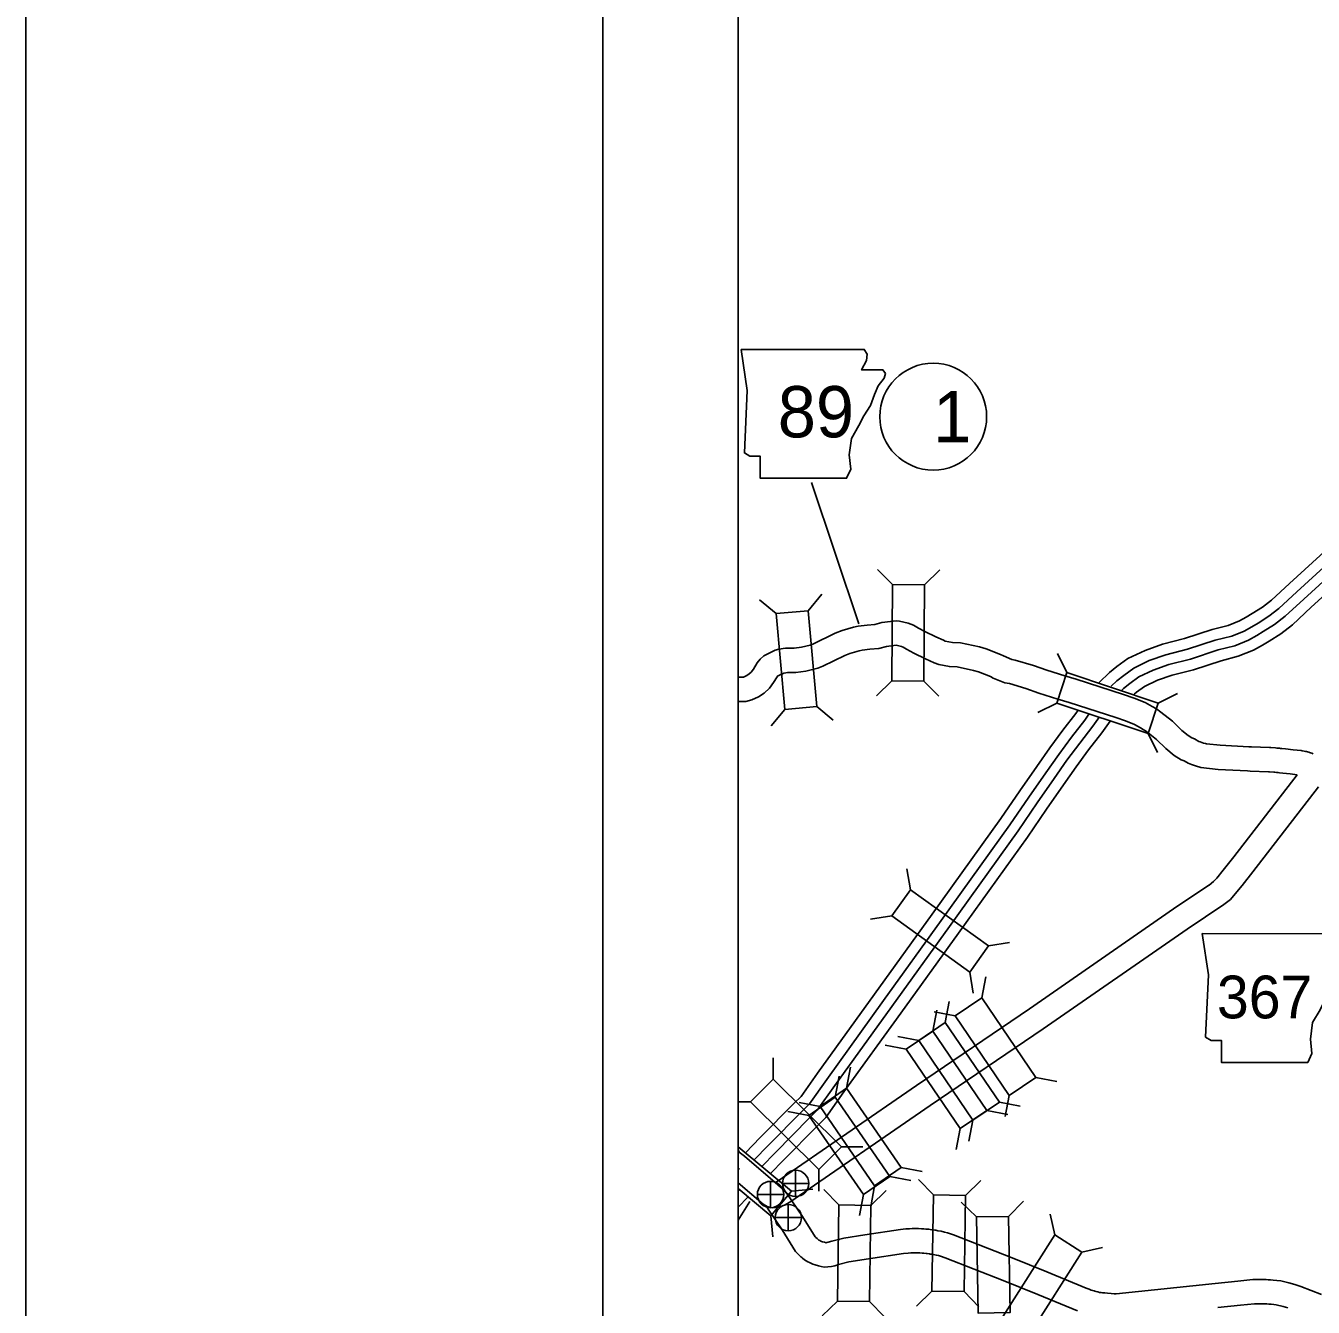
# Model space of a CAD drawing. Extents: x 1367863 to 1368197, y 380048 to 380261.
# Drawn here: x 1367863.39 to 1367891.07, y 380206.32 to 380233.88 of the extents above; entities that cross this region are included whole.
import ezdxf

# ---------------------------------------------------------------- set-up
doc = ezdxf.new("R2010")
doc.units = 0
for name, color, linetype in [('Level 10', 7, 'Continuous'), ('Level 15', 7, 'Continuous'), ('Level 20', 7, 'Continuous'), ('Level 21', 7, 'Continuous'), ('Level 26', 7, 'Continuous'), ('Level 27', 7, 'Continuous'), ('Level 58', 7, 'Continuous'), ('R_Border', 7, 'Continuous'), ('R_No Plot', 7, 'Continuous')]:
    doc.layers.add(name, color=color, linetype=linetype)

msp = doc.modelspace()

# ---------------------------------------------------------------- linework, layer by layer
at = {"layer": 'Level 10'}
for points in [[(1367878.711, 380219.865), (1367878.808, 380219.866), (1367878.824, 380219.87), (1367878.896, 380219.905), (1367878.945, 380219.936), (1367878.989, 380219.977), (1367879.035, 380220.042), (1367879.119, 380220.176), (1367879.181, 380220.254), (1367879.264, 380220.326), (1367879.348, 380220.373), (1367879.507, 380220.446), (1367879.586, 380220.469), (1367879.729, 380220.489), (1367879.913, 380220.493), (1367880.069, 380220.512), (1367880.26, 380220.557), (1367880.312, 380220.578), (1367880.792, 380220.814), (1367880.945, 380220.871), (1367881.189, 380220.941), (1367881.287, 380220.961), (1367881.48, 380220.988), (1367881.645, 380221.003), (1367881.8, 380221.042), (1367882.105, 380221.079), (1367882.175, 380221.073), (1367882.365, 380221.027), (1367882.481, 380220.989), (1367882.588, 380220.923), (1367882.725, 380220.848), (1367882.959, 380220.733), (1367883.123, 380220.66), (1367883.162, 380220.645), (1367883.317, 380220.616), (1367883.49, 380220.606), (1367883.896, 380220.519), (1367884.042, 380220.476), (1367884.35, 380220.357), (1367884.412, 380220.324), (1367884.593, 380220.251), (1367884.667, 380220.236), (1367885.057, 380220.121), (1367885.346, 380220.015), (1367885.729, 380219.893), (1367885.974, 380219.823), (1367886.995, 380219.495), (1367887.221, 380219.417), (1367887.459, 380219.32), (1367887.612, 380219.236)], [(1367878.711, 380219.343), (1367878.875, 380219.344), (1367879.006, 380219.378), (1367879.149, 380219.447), (1367879.267, 380219.522), (1367879.383, 380219.631), (1367879.469, 380219.75), (1367879.547, 380219.875), (1367879.561, 380219.893), (1367879.565, 380219.896), (1367879.584, 380219.906), (1367879.691, 380219.956), (1367879.697, 380219.957), (1367879.77, 380219.968), (1367879.951, 380219.971), (1367880.161, 380219.998), (1367880.419, 380220.058), (1367880.526, 380220.102), (1367880.999, 380220.333), (1367881.109, 380220.374), (1367881.313, 380220.433), (1367881.376, 380220.446), (1367881.54, 380220.469), (1367881.733, 380220.486), (1367881.897, 380220.528), (1367882.104, 380220.553), (1367882.222, 380220.524), (1367882.259, 380220.512), (1367882.325, 380220.471), (1367882.485, 380220.384), (1367882.737, 380220.26), (1367882.925, 380220.176), (1367883.023, 380220.14), (1367883.252, 380220.097), (1367883.419, 380220.087), (1367883.767, 380220.012), (1367883.873, 380219.981), (1367884.135, 380219.88), (1367884.194, 380219.849), (1367884.442, 380219.749), (1367884.54, 380219.729), (1367884.893, 380219.625), (1367885.176, 380219.521), (1367885.578, 380219.392), (1367885.823, 380219.323), (1367886.83, 380218.999), (1367887.038, 380218.928), (1367887.233, 380218.849), (1367887.358, 380218.779)], [(1367887.612, 380219.236), (1367887.699, 380219.184), (1367887.797, 380219.117), (1367888.044, 380218.919), (1367888.25, 380218.724), (1367888.385, 380218.61), (1367888.463, 380218.565), (1367888.519, 380218.543), (1367888.616, 380218.488), (1367888.641, 380218.477), (1367888.714, 380218.452), (1367888.755, 380218.445), (1367888.776, 380218.437), (1367889.07, 380218.406), (1367889.685, 380218.373), (1367889.744, 380218.37), (1367890.135, 380218.353), (1367890.161, 380218.352), (1367890.258, 380218.346), (1367890.286, 380218.344), (1367890.323, 380218.341), (1367890.346, 380218.339), (1367890.367, 380218.337), (1367890.397, 380218.334), (1367890.473, 380218.326), (1367890.638, 380218.307), (1367890.81, 380218.288), (1367890.833, 380218.285), (1367890.875, 380218.278), (1367890.905, 380218.272), (1367890.927, 380218.267), (1367890.952, 380218.26), (1367890.975, 380218.253), (1367890.993, 380218.247), (1367891.013, 380218.241), (1367891.039, 380218.231), (1367891.072, 380218.218)], [(1367887.358, 380218.779), (1367887.418, 380218.744), (1367887.486, 380218.697), (1367887.701, 380218.525), (1367887.901, 380218.334), (1367888.083, 380218.181), (1367888.235, 380218.093), (1367888.294, 380218.07), (1367888.383, 380218.02), (1367888.453, 380217.99), (1367888.582, 380217.945), (1367888.616, 380217.939), (1367888.656, 380217.924), (1367889.029, 380217.885), (1367889.657, 380217.852), (1367889.719, 380217.849), (1367890.111, 380217.832), (1367890.132, 380217.831), (1367890.222, 380217.825), (1367890.246, 380217.823), (1367890.28, 380217.82), (1367890.3, 380217.819), (1367890.318, 380217.817), (1367890.345, 380217.814), (1367890.416, 380217.807), (1367890.579, 380217.788), (1367890.727, 380217.771)], [(1367878.731, 380209.657), (1367878.842, 380209.568), (1367879.505, 380209.003), (1367879.544, 380209.024), (1367882.545, 380211.089), (1367884.972, 380212.738), (1367888.068, 380214.884), (1367888.829, 380215.392), (1367888.835, 380215.395), (1367888.931, 380215.471), (1367889.001, 380215.548), (1367889.136, 380215.715), (1367889.363, 380216.003), (1367890.727, 380217.771)], [(1367878.711, 380208.994), (1367879.246, 380208.537), (1367879.335, 380208.483), (1367879.446, 380208.46), (1367879.517, 380208.465), (1367879.586, 380208.474), (1367879.703, 380208.516), (1367879.817, 380208.577), (1367882.84, 380210.657), (1367885.268, 380212.307), (1367888.361, 380214.452), (1367889.151, 380214.979), (1367889.29, 380215.089), (1367889.397, 380215.208), (1367889.544, 380215.389), (1367889.775, 380215.682), (1367891.186, 380217.512)], [(1367878.711, 380209.714), (1367878.731, 380209.657)], [(1367879.505, 380209.003), (1367879.616, 380208.905), (1367879.653, 380208.876), (1367879.743, 380208.784), (1367879.864, 380208.605)], [(1367879.26, 380208.52), (1367879.295, 380208.492), (1367879.306, 380208.484), (1367879.337, 380208.452), (1367879.656, 380207.983), (1367879.945, 380207.521), (1367879.983, 380207.478), (1367880.02, 380207.437), (1367880.042, 380207.421), (1367880.059, 380207.405), (1367880.075, 380207.391), (1367880.093, 380207.375), (1367880.138, 380207.341), (1367880.173, 380207.32), (1367880.207, 380207.299), (1367880.239, 380207.281), (1367880.271, 380207.264), (1367880.317, 380207.246), (1367880.367, 380207.228), (1367880.435, 380207.211), (1367880.496, 380207.195), (1367880.561, 380207.184), (1367880.635, 380207.185), (1367880.718, 380207.197), (1367880.784, 380207.213), (1367880.866, 380207.239), (1367881.086, 380207.295), (1367881.512, 380207.359), (1367882.266, 380207.472), (1367882.362, 380207.482), (1367882.421, 380207.486), (1367882.48, 380207.489), (1367882.492, 380207.49), (1367882.528, 380207.49), (1367882.561, 380207.489), (1367882.617, 380207.486), (1367882.667, 380207.482), (1367882.702, 380207.48), (1367882.749, 380207.475), (1367882.773, 380207.472), (1367882.813, 380207.468), (1367882.824, 380207.467), (1367882.839, 380207.463), (1367882.871, 380207.458), (1367882.908, 380207.452), (1367882.966, 380207.441), (1367883.016, 380207.43), (1367883.057, 380207.418), (1367883.161, 380207.384), (1367884.408, 380206.896), (1367885.15, 380206.595), (1367886.004, 380206.243)], [(1367879.864, 380208.605), (1367880.093, 380208.268), (1367880.364, 380207.835), (1367880.371, 380207.828), (1367880.373, 380207.825), (1367880.379, 380207.821), (1367880.406, 380207.795), (1367880.419, 380207.785), (1367880.426, 380207.779), (1367880.432, 380207.774), (1367880.446, 380207.765), (1367880.468, 380207.752), (1367880.488, 380207.741), (1367880.493, 380207.738), (1367880.504, 380207.734), (1367880.521, 380207.728), (1367880.562, 380207.717), (1367880.601, 380207.707), (1367880.617, 380207.71), (1367880.642, 380207.716), (1367880.723, 380207.742), (1367880.982, 380207.808), (1367881.435, 380207.876), (1367882.201, 380207.99), (1367882.316, 380208.002), (1367882.389, 380208.008), (1367882.451, 380208.011), (1367882.473, 380208.012), (1367882.538, 380208.012), (1367882.586, 380208.01), (1367882.649, 380208.007), (1367882.702, 380208.003), (1367882.743, 380208.001), (1367882.808, 380207.995), (1367882.837, 380207.991), (1367882.869, 380207.987), (1367882.904, 380207.984), (1367882.935, 380207.977), (1367882.956, 380207.974), (1367883.001, 380207.966), (1367883.071, 380207.953), (1367883.147, 380207.936), (1367883.212, 380207.917), (1367883.336, 380207.877), (1367884.601, 380207.381), (1367885.348, 380207.078), (1367886.193, 380206.731), (1367886.255, 380206.708), (1367886.301, 380206.69), (1367886.328, 380206.681), (1367886.36, 380206.669), (1367886.378, 380206.664), (1367886.403, 380206.657), (1367886.438, 380206.649), (1367886.476, 380206.639), (1367886.495, 380206.635), (1367886.51, 380206.634), (1367886.544, 380206.631), (1367886.595, 380206.626), (1367886.648, 380206.621), (1367886.726, 380206.614), (1367886.795, 380206.608), (1367886.832, 380206.608), (1367888.966, 380206.831), (1367889.451, 380206.882), (1367889.771, 380206.916), (1367889.837, 380206.918), (1367889.868, 380206.918), (1367889.91, 380206.918), (1367889.954, 380206.918), (1367890.005, 380206.918), (1367890.063, 380206.914), (1367890.102, 380206.912), (1367890.156, 380206.908), (1367890.208, 380206.905), (1367890.287, 380206.896), (1367890.372, 380206.885), (1367890.546, 380206.842), (1367890.679, 380206.81), (1367890.802, 380206.763), (1367891.251, 380206.597)], [(1367889.021, 380206.312), (1367889.505, 380206.363), (1367889.808, 380206.395), (1367889.847, 380206.396), (1367889.866, 380206.396), (1367889.91, 380206.396), (1367889.954, 380206.396), (1367889.984, 380206.396), (1367890.036, 380206.392), (1367890.071, 380206.391), (1367890.119, 380206.387), (1367890.165, 380206.384), (1367890.224, 380206.378), (1367890.275, 380206.371), (1367890.423, 380206.335), (1367890.523, 380206.31)]]:
    msp.add_lwpolyline(points, dxfattribs=at)
at = {"layer": 'Level 15'}
for points in [[(1367886.472, 380219.756), (1367886.689, 380219.965), (1367886.852, 380220.097), (1367887.089, 380220.27), (1367887.456, 380220.444), (1367887.832, 380220.579), (1367888.303, 380220.698), (1367888.897, 380220.891), (1367889.245, 380220.981), (1367889.485, 380221.076), (1367889.628, 380221.157), (1367889.759, 380221.236), (1367889.978, 380221.373), (1367890.175, 380221.525), (1367890.559, 380221.882), (1367891.967, 380223.166), (1367892.459, 380223.625), (1367893.445, 380224.541)], [(1367886.73, 380219.672), (1367886.848, 380219.786), (1367886.998, 380219.907), (1367887.212, 380220.063), (1367887.548, 380220.223), (1367887.902, 380220.35), (1367888.37, 380220.468), (1367888.964, 380220.661), (1367889.319, 380220.752), (1367889.589, 380220.859), (1367889.749, 380220.95), (1367889.885, 380221.032), (1367890.115, 380221.177), (1367890.33, 380221.342), (1367890.721, 380221.706), (1367892.129, 380222.99), (1367892.622, 380223.449), (1367893.616, 380224.373)], [(1367886.958, 380219.59), (1367886.992, 380219.623), (1367887.13, 380219.734), (1367887.324, 380219.875), (1367887.632, 380220.021), (1367887.966, 380220.142), (1367888.43, 380220.258), (1367889.025, 380220.452), (1367889.386, 380220.545), (1367889.683, 380220.662), (1367889.859, 380220.763), (1367889.999, 380220.847), (1367890.24, 380220.998), (1367890.471, 380221.176), (1367890.868, 380221.546), (1367892.277, 380222.83), (1367892.771, 380223.29), (1367893.784, 380224.233)], [(1367887.225, 380219.503), (1367887.276, 380219.544), (1367887.447, 380219.669), (1367887.724, 380219.8), (1367888.036, 380219.912), (1367888.496, 380220.028), (1367889.092, 380220.222), (1367889.461, 380220.317), (1367889.787, 380220.446), (1367889.98, 380220.556), (1367890.124, 380220.643), (1367890.377, 380220.801), (1367890.626, 380220.993), (1367891.031, 380221.37), (1367892.439, 380222.654), (1367892.934, 380223.115), (1367893.948, 380224.058)], [(1367878.866, 380209.64), (1367879.181, 380209.969), (1367879.915, 380210.708), (1367880.06, 380210.852), (1367880.417, 380211.354), (1367881.641, 380213.052), (1367882.88, 380214.773), (1367884.355, 380216.827), (1367884.763, 380217.427), (1367885.13, 380217.95), (1367885.407, 380218.346), (1367885.686, 380218.725), (1367885.968, 380219.089), (1367886.015, 380219.156)], [(1367879.051, 380209.486), (1367879.353, 380209.801), (1367880.084, 380210.539), (1367880.243, 380210.696), (1367880.612, 380211.215), (1367881.835, 380212.912), (1367883.074, 380214.633), (1367884.552, 380216.69), (1367884.96, 380217.291), (1367885.326, 380217.813), (1367885.601, 380218.207), (1367885.877, 380218.58), (1367886.16, 380218.946), (1367886.251, 380219.075)], [(1367879.218, 380209.347), (1367879.509, 380209.649), (1367880.238, 380210.385), (1367880.41, 380210.555), (1367880.789, 380211.088), (1367882.011, 380212.784), (1367883.251, 380214.506), (1367884.73, 380216.565), (1367885.14, 380217.167), (1367885.505, 380217.688), (1367885.778, 380218.08), (1367886.051, 380218.449), (1367886.335, 380218.817), (1367886.476, 380219.014)], [(1367879.403, 380209.193), (1367879.68, 380209.482), (1367880.407, 380210.216), (1367880.593, 380210.399), (1367880.984, 380210.948), (1367882.206, 380212.645), (1367883.445, 380214.366), (1367884.926, 380216.428), (1367885.337, 380217.031), (1367885.701, 380217.551), (1367885.972, 380217.94), (1367886.242, 380218.305), (1367886.527, 380218.674), (1367886.706, 380218.924)], [(1367878.711, 380208.819), (1367878.743, 380208.852)], [(1367878.711, 380208.474), (1367878.918, 380208.689)]]:
    msp.add_lwpolyline(points, dxfattribs=at)
at = {"layer": 'Level 20'}
for p, q in [((1367882.024, 380221.859), (1367881.701, 380222.186)), ((1367882.713, 380221.853), (1367883.041, 380222.176)), ((1367879.524, 380221.234), (1367879.171, 380221.529)), ((1367880.211, 380221.297), (1367880.505, 380221.65)), ((1367885.778, 380219.966), (1367885.572, 380220.377)), ((1367882.009, 380219.79), (1367881.681, 380219.467)), ((1367882.698, 380219.785), (1367883.021, 380219.458)), ((1367885.56, 380219.312), (1367885.148, 380219.106)), ((1367887.74, 380219.311), (1367888.151, 380219.516)), ((1367879.711, 380219.174), (1367879.416, 380218.821)), ((1367880.397, 380219.236), (1367880.75, 380218.942)), ((1367887.522, 380218.657), (1367887.727, 380218.246)), ((1367882.411, 380215.297), (1367882.338, 380215.75)), ((1367882.009, 380214.737), (1367881.555, 380214.663)), ((1367884.09, 380214.088), (1367884.544, 380214.162)), ((1367883.687, 380213.528), (1367883.761, 380213.075)), ((1367883.945, 380212.974), (1367884.031, 380213.426)), ((1367882.892, 380212.259), (1367882.978, 380212.711)), ((1367883.375, 380212.587), (1367882.923, 380212.673)), ((1367883.161, 380212.442), (1367883.247, 380212.893)), ((1367882.591, 380212.054), (1367882.139, 380212.14)), ((1367882.322, 380211.872), (1367881.87, 380211.958)), ((1367879.46, 380211.224), (1367879.458, 380211.684)), ((1367880.796, 380210.836), (1367880.879, 380211.288)), ((1367881.037, 380211.028), (1367881.121, 380211.48)), ((1367885.108, 380211.263), (1367885.559, 380211.177)), ((1367878.974, 380210.734), (1367878.711, 380210.733)), ((1367880.469, 380210.637), (1367880.017, 380210.72)), ((1367884.324, 380210.731), (1367884.775, 380210.644)), ((1367884.537, 380210.876), (1367884.451, 380210.424)), ((1367880.228, 380210.445), (1367879.776, 380210.529)), ((1367884.055, 380210.548), (1367884.506, 380210.462)), ((1367883.484, 380210.16), (1367883.398, 380209.709)), ((1367883.753, 380210.343), (1367883.667, 380209.892)), ((1367880.929, 380209.768), (1367881.389, 380209.77)), ((1367882.21, 380209.323), (1367882.662, 380209.24)), ((1367880.444, 380209.278), (1367880.446, 380208.818)), ((1367881.968, 380209.132), (1367882.42, 380209.048)), ((1367882.906, 380208.734), (1367882.586, 380209.063)), ((1367879.854, 380208.817), (1367880.312, 380208.859)), ((1367880.874, 380208.521), (1367880.554, 380208.851)), ((1367881.642, 380208.933), (1367881.558, 380208.481)), ((1367881.564, 380208.51), (1367881.894, 380208.83)), ((1367883.595, 380208.723), (1367883.925, 380209.043)), ((1367881.4, 380208.741), (1367881.317, 380208.289)), ((1367883.834, 380208.262), (1367883.504, 380208.582)), ((1367884.523, 380208.272), (1367884.843, 380208.602)), ((1367879.413, 380208.287), (1367879.454, 380207.83)), ((1367885.514, 380207.873), (1367885.413, 380208.322)), ((1367886.096, 380207.504), (1367886.545, 380207.604)), ((1367882.875, 380206.665), (1367882.545, 380206.345)), ((1367883.565, 380206.655), (1367883.885, 380206.325)), ((1367880.842, 380206.452), (1367880.512, 380206.132)), ((1367881.532, 380206.442), (1367881.852, 380206.112))]:
    msp.add_line(p, q, dxfattribs=at)
for points in [[(1367882.024, 380221.859), (1367882.009, 380219.79), (1367882.698, 380219.785), (1367882.713, 380221.853)], [(1367879.524, 380221.234), (1367879.711, 380219.174), (1367880.397, 380219.236), (1367880.211, 380221.297)], [(1367887.74, 380219.311), (1367885.778, 380219.966), (1367885.56, 380219.312), (1367887.522, 380218.657)], [(1367882.009, 380214.737), (1367883.687, 380213.528), (1367884.09, 380214.088), (1367882.411, 380215.297)], [(1367883.375, 380212.587), (1367884.537, 380210.876), (1367885.108, 380211.263), (1367883.945, 380212.974)], [(1367882.591, 380212.054), (1367883.753, 380210.343), (1367884.324, 380210.731), (1367883.161, 380212.442)], [(1367884.055, 380210.548), (1367882.892, 380212.259), (1367882.322, 380211.872), (1367883.484, 380210.16)], [(1367880.929, 380209.768), (1367879.46, 380211.224), (1367878.974, 380210.734), (1367880.444, 380209.278)], [(1367882.21, 380209.323), (1367881.037, 380211.028), (1367880.469, 380210.637), (1367881.642, 380208.933)], [(1367880.228, 380210.445), (1367881.4, 380208.741), (1367881.968, 380209.132), (1367880.796, 380210.836)], [(1367881.532, 380206.442), (1367881.564, 380208.51), (1367880.874, 380208.521), (1367880.842, 380206.452)], [(1367882.906, 380208.734), (1367882.875, 380206.665), (1367883.565, 380206.655), (1367883.595, 380208.723)], [(1367883.834, 380208.262), (1367883.865, 380206.193), (1367884.555, 380206.204), (1367884.523, 380208.272)], [(1367885.514, 380207.873), (1367884.406, 380206.126), (1367884.988, 380205.757), (1367886.096, 380207.504)]]:
    msp.add_lwpolyline(points, close=True, dxfattribs=at)
msp.add_lwpolyline([(1367878.711, 380208.872), (1367879.413, 380208.287), (1367879.854, 380208.817), (1367878.711, 380209.769)], dxfattribs=at)
at = {"layer": 'Level 21'}
msp.add_line((1367880.287, 380224.051), (1367881.305, 380221.014), dxfattribs=at)
for points in [[(1367878.771, 380226.915), (1367878.904, 380226.031), (1367878.845, 380224.691), (1367878.963, 380224.617), (1367879.184, 380224.617), (1367879.184, 380224.146), (1367881.039, 380224.146), (1367881.128, 380224.338), (1367881.098, 380224.647), (1367881.143, 380225), (1367881.305, 380225.28), (1367881.408, 380225.486), (1367881.555, 380225.707), (1367881.643, 380225.943), (1367881.717, 380226.134), (1367881.85, 380226.296), (1367881.879, 380226.4), (1367881.82, 380226.473), (1367881.363, 380226.473), (1367881.467, 380226.679), (1367881.481, 380226.812), (1367881.42, 380226.914)], [(1367888.685, 380214.353), (1367888.818, 380213.47), (1367888.759, 380212.129), (1367888.877, 380212.056), (1367889.098, 380212.056), (1367889.098, 380211.584), (1367890.954, 380211.584), (1367891.042, 380211.776), (1367891.013, 380212.085), (1367891.057, 380212.439), (1367891.219, 380212.718), (1367891.322, 380212.925), (1367891.469, 380213.146), (1367891.557, 380213.381), (1367891.631, 380213.573), (1367891.764, 380213.735), (1367891.793, 380213.838), (1367891.734, 380213.911), (1367891.278, 380213.911), (1367891.381, 380214.118), (1367891.395, 380214.25), (1367891.334, 380214.352)]]:
    msp.add_lwpolyline(points, close=True, dxfattribs=at)
at = {"layer": 'Level 26'}
for p, q in [((1367879.944, 380208.699), (1367879.944, 380209.265)), ((1367879.405, 380208.46), (1367879.405, 380209.025)), ((1367879.661, 380208.982), (1367880.227, 380208.982)), ((1367879.122, 380208.743), (1367879.688, 380208.743)), ((1367879.787, 380207.963), (1367879.787, 380208.529)), ((1367879.504, 380208.246), (1367880.07, 380208.246))]:
    msp.add_line(p, q, dxfattribs=at)
for centre in [(1367879.944, 380208.982), (1367879.405, 380208.743), (1367879.787, 380208.246)]:
    msp.add_circle(centre, 0.283, dxfattribs=at)
at = {"layer": 'Level 27'}
msp.add_circle((1367882.902, 380225.469), 1.149, dxfattribs=at)
at = {"layer": 'Level 58'}
msp.add_line((1367878.711, 380209.296), (1367878.741, 380209.297), dxfattribs=at)
msp.add_lwpolyline([(1367878.711, 380208.192), (1367878.958, 380208.592)], dxfattribs=at)
at = {"layer": 'R_Border'}
msp.add_line((1367875.8, 380052.084), (1367875.8, 380257.536), dxfattribs=at)
at = {"layer": 'R_No Plot'}
for points in [[(1367863.393, 380261.431), (1368196.721, 380261.431), (1368196.721, 380048.101), (1367863.393, 380048.101)], [(1367878.711, 380254.093), (1367937.876, 380254.093), (1367937.876, 380187.495), (1367878.711, 380187.495)]]:
    msp.add_lwpolyline(points, close=True, dxfattribs=at)

# ---------------------------------------------------------------- texts
at = {"layer": 'Level 21'}
for s, height, p in [('89', 1.1032, (1367879.56, 380225.024)), ('367', 0.9194, (1367889.002, 380212.531))]:
    msp.add_text(s, height=height, dxfattribs=at).set_placement(p)
at = {"layer": 'Level 27'}
msp.add_text('1', height=1.103, dxfattribs=at).set_placement((1367882.902, 380224.917))

doc.saveas('drawing.dxf')
